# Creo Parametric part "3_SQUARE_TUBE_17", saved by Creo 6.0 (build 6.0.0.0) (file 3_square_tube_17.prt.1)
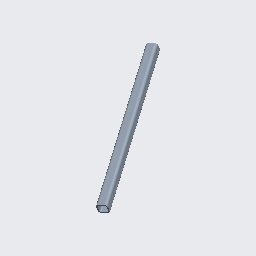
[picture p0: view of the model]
Units: Custom; MM, KILOGRAM, SECS
Materials in the file: STEEL

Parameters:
  BUW_NAME = "SQUARE TUBE"
  BUW_TYPE = "DIN EN 10219"
  BUW_SIZE = "25x25x3.0"
  BUW_LENGTH_STR = "410"
  PTC_MATERIAL_NAME = "STEEL"
  BUW_PROFIL_TYPE = "square_tube"
  BUW_PROFILE_PATH = "parts//profiles/steel_beams_mm/"
  BUW_PROFILE_NAME_LANG = "SQUARE TUBE"
  BUW_TAB_SEL_INFO = "-2 TYPE DIN_EN_10219-1997 SIZE_DINEN_10219 25x25x3.0"
  NAMING = "SQUARE TUBE"
  DESIGNATION = "DIN EN 10219 25x25x3.0 x 410"
  PROFIL_RASTER_POS = "X_0"
  BUW_OBJECT_ROLE = "PROFIL_SYSTEM_BORE_END_POINTS"
  PRO_UNIT_SYS = "Custom"

Other parameters: BUW_LENGTH, LENGTH, BUW_LENGTH_Z_MIN_PARAM, D8, D93, D94, d26, d8, d93, d94, d98, D98, SHEAR_MODULUS, THERM_EXPANSION_REF_TEMPERATURE, STRUCTURAL_DAMPING_COEFFICIENT, STRESS_LIMIT_FOR_TENSION, STRESS_LIMIT_FOR_COMPRESSION, STRESS_LIMIT_FOR_SHEAR, EMISSIVITY

Created from: SQUARE_TUBE.PRT

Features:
  1. datum plane "YZ"
  2. datum plane "XZ"
  3. datum plane "XY"
  4. coordinate system
  5. coordinate system
  6. coordinate system
  7. coordinate system
  8. datum plane "DTM3"
  9. datum plane "DTM4"
  10. datum plane "DTM5"
  11. protrusion
  12. round
  13. round
  14. datum axis
  15. datum point "PNT0"
  16. datum point

Other named items: PROFIL_CUT_QUILT, PROFILE_LENGTH_DIM, CONTACT_SURF_3, CONTACT_SURF_2, CONTACT_SURF_1, CONTACT_SURF_0, E, START_SURFACE, END_SURFACE, SIDE_SURF_3, SIDE_SURF_0, SIDE_SURF_1, SIDE_SURF_2, EDGE_7_S, EDGE_7_E, EDGE_1_S, EDGE_1_E, EDGE_3_S, EDGE_3_E, EDGE_5_S, EDGE_5_E, EDGE_6_S, EDGE_4_S, EDGE_2_S, EDGE_0_S, EDGE_6_E, EDGE_4_E, EDGE_2_E, EDGE_0_E, CS0, CS_S, CS_E, CS3

Named dimensions: X_ROT_S, Y_ROT_S, Z_OFF_S, X_ROT_E, Y_ROT_E, Z_OFF_E, PC_L, BUW_LENGTH_Z_MIN, BUW_LENGTH_DIM

Layers: 00_PROFIL_DATUM, 00_PROFIL_DRW_HIDE, 00_PROFIL_END_CSYS, 00_PROFIL_GEOMETRY, 00_PROFIL_QUILT, 00_PROFIL_SIZE_NOTE

Surfaces: 16 plane, 12 cylinder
